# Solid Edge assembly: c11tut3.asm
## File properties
Author: CADCIM
Template: iso assembly.asm
Last saved by: CADCIM
Revision: 16
Application: Solid Edge
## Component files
Casting.par
Brasses.par
cap.par
Bolt.par
Nut.par
Lock Nut.par
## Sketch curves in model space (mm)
line (-97.5, -28, 0) -> (-97.5, -28, 2)
line (-97.5, -28, 2) -> (97.5, -28, 2)
line (97.5, -28, 2) -> (97.5, -28, 0)
line (97.5, -28, 0) -> (0, -28, 0)
line (0, -28, 0) -> (-97.5, -28, 0)
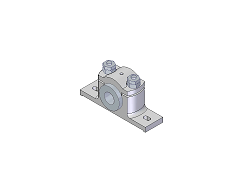
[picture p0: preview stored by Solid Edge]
